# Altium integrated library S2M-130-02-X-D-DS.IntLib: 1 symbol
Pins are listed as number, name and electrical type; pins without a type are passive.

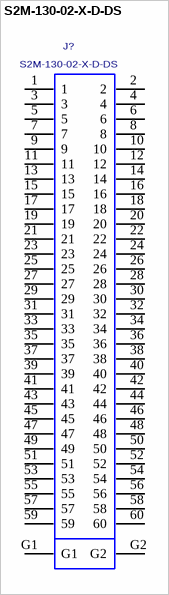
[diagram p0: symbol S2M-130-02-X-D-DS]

## S2M-130-02-X-D-DS
designator J?
2mm DOUBLE ROW SOCKET STRIP, 60 Pins, Dual Screw Down.; MANUFACTURER: SAMTEC
footprint S2M-130-02-X-D-DS
pins: 1, 2, 3, 4, 5, 6, 7, 8, 9, 10, 11, 12, 13, 14, 15, 16, 17, 18, 19, 20, 21, 22, 23, 24, 25, 26, 27, 28, 29, 30, 31, 32, 33, 34, 35, 36, 37, 38, 39, 40, 41, 42, 43, 44, 45, 46, 47, 48, 49, 50, 51, 52, 53, 54, 55, 56, 57, 58, 59, 60, G1, G2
